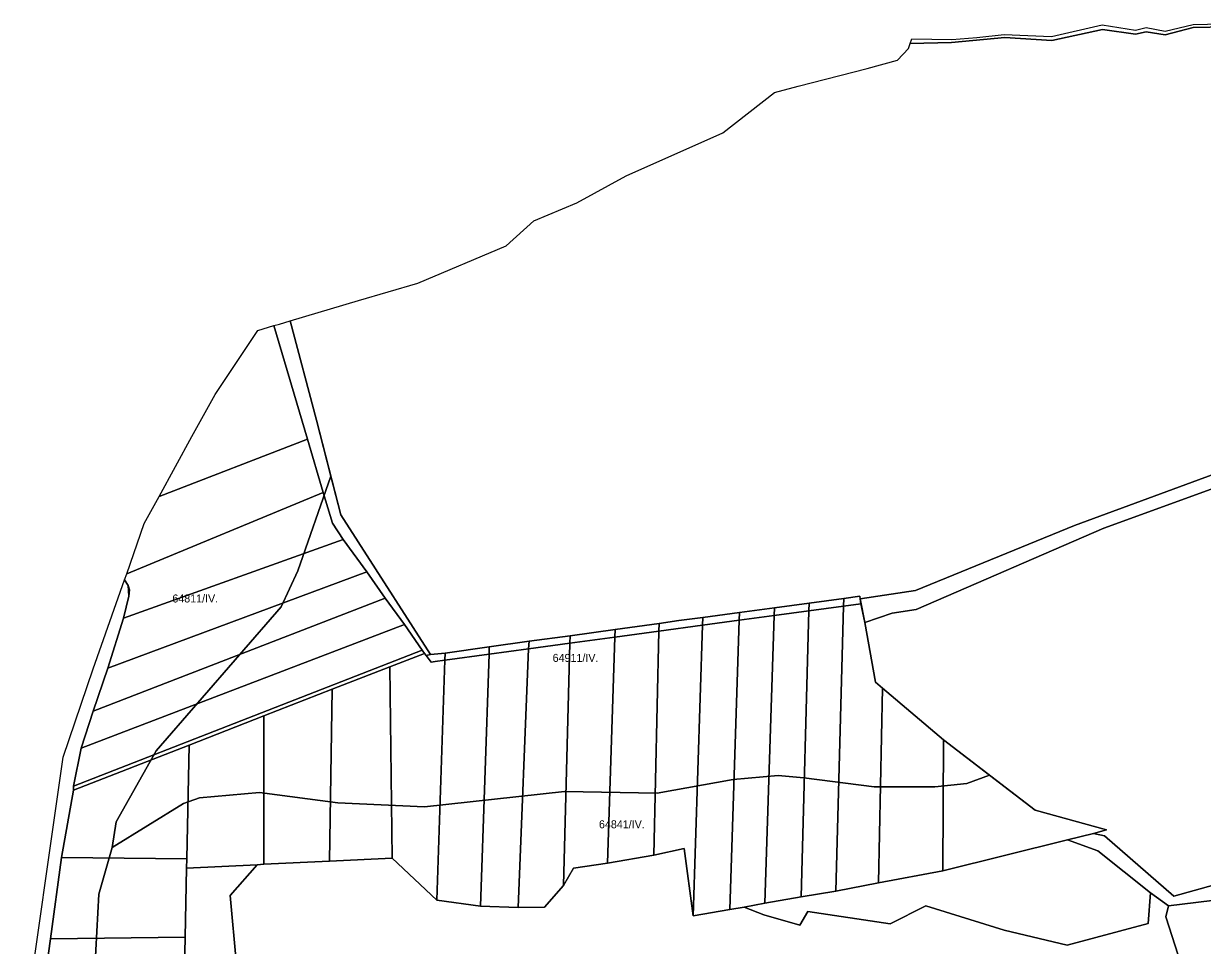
# Model space of a CAD drawing. Extents: x -521261 to -517465, y -1182764 to -1179456.
# Drawn here: x -521236 to -520500, y -1180889 to -1180313 of the extents above; entities that cross this region are included whole.
import ezdxf

# ---------------------------------------------------------------- set-up
doc = ezdxf.new("R2010")
doc.units = 0
for name, color, linetype in [('95560013', 7, 'Continuous'), ('95620013', 7, 'Continuous'), ('95630013', 7, 'Continuous'), ('95640013', 7, 'Continuous'), ('95660013', 7, 'Continuous')]:
    doc.layers.add(name, color=color, linetype=linetype)

msp = doc.modelspace()

# ---------------------------------------------------------------- linework, layer by layer
at = {"layer": '95560013'}
for points in [[(-521080, -1180501.82), (-521059.04, -1180572.8), (-521151.7, -1180608.67), (-521131.22, -1180571.13), (-521116.74, -1180544.81), (-521090.08, -1180504.84)], [(-521059.04, -1180572.8), (-521049.31, -1180606.17), (-521171.97, -1180656.94), (-521160.99, -1180625.55), (-521151.7, -1180608.67)], [(-521043.32, -1180625.33), (-521036.66, -1180635.53), (-521173.94, -1180684.6), (-521170.63, -1180670.86), (-521170.22, -1180666.94), (-521171, -1180664.15), (-521173.37, -1180660.62), (-521171.97, -1180656.94), (-521049.31, -1180606.17)], [(-521036.66, -1180635.53), (-521022.04, -1180655.73), (-521183.82, -1180715.79), (-521173.94, -1180684.6)], [(-521022.04, -1180655.73), (-521010.53, -1180672.06), (-521193.01, -1180742.64), (-521183.82, -1180715.79)], [(-521171, -1180664.15), (-521170.22, -1180666.94), (-521170.63, -1180670.86)], [(-521010.53, -1180672.06), (-520998.52, -1180688.54), (-521200.55, -1180765.87), (-521193.01, -1180742.64)], [(-520767.51, -1180682.98), (-520745.79, -1180680.06), (-520750.61, -1180858.87), (-520773.26, -1180862.77)], [(-520745.79, -1180680.06), (-520724.15, -1180677.17), (-520728.86, -1180855.3), (-520750.61, -1180858.87)], [(-520724.15, -1180677.17), (-520713.2, -1180675.69), (-520710.85, -1180687.4), (-520704.09, -1180724.52), (-520699.81, -1180728.35), (-520702.34, -1180849.97), (-520728.86, -1180855.3)], [(-520987.41, -1180704.59), (-521205.18, -1180789.6), (-521200.55, -1180765.87), (-520998.52, -1180688.54)], [(-520839.43, -1180692.75), (-520812.13, -1180689.06), (-520818.13, -1180870.65), (-520823.65, -1180828.61), (-520842.59, -1180832.65)], [(-520812.13, -1180689.06), (-520789.27, -1180685.97), (-520795.24, -1180866.73), (-520818.13, -1180870.65)], [(-520789.27, -1180685.97), (-520767.51, -1180682.98), (-520773.26, -1180862.77), (-520786.22, -1180865.2), (-520795.24, -1180866.73)], [(-520895.11, -1180700.28), (-520867, -1180696.48), (-520871.59, -1180837.65), (-520892.8, -1180840.93), (-520899.15, -1180851.67)], [(-520867, -1180696.48), (-520839.43, -1180692.75), (-520842.59, -1180832.65), (-520871.59, -1180837.65)], [(-520945.47, -1180707.08), (-520920.86, -1180703.75), (-520927.48, -1180865.42), (-520950.88, -1180864.7)], [(-520920.86, -1180703.75), (-520895.11, -1180700.28), (-520899.15, -1180851.67), (-520910.87, -1180865.15), (-520927.48, -1180865.42)], [(-520985.98, -1180706.63), (-521007.56, -1180714.96), (-521043.67, -1180729.02), (-521086.26, -1180745.67), (-521132.89, -1180763.92), (-521205.35, -1180792.14), (-521205.18, -1180789.6), (-520987.41, -1180704.59)], [(-520984.95, -1180708.02), (-520981.77, -1180712.2), (-520979.3, -1180711.65), (-520973.23, -1180710.84), (-520978.13, -1180860.76), (-521006.09, -1180834.57), (-521007.56, -1180714.96), (-520985.98, -1180706.63)], [(-520973.23, -1180710.84), (-520945.47, -1180707.08), (-520950.88, -1180864.7), (-520978.13, -1180860.76)], [(-521007.56, -1180714.96), (-521006.09, -1180834.57), (-521045.3, -1180836.39), (-521043.67, -1180729.02)], [(-521043.67, -1180729.02), (-521045.3, -1180836.39), (-521086.39, -1180838.41), (-521086.26, -1180745.67)], [(-520661.61, -1180760.58), (-520662.13, -1180842.53), (-520702.34, -1180849.97), (-520699.81, -1180728.35)], [(-521086.26, -1180745.67), (-521086.39, -1180838.41), (-521090.43, -1180838.7), (-521134.59, -1180840.77), (-521134.36, -1180835.02), (-521132.89, -1180763.92)], [(-520604.38, -1180804.7), (-520559.81, -1180816.94), (-520567.99, -1180819.26), (-520584.27, -1180823.22), (-520662.13, -1180842.53), (-520661.61, -1180760.58)], [(-521132.89, -1180763.92), (-521134.36, -1180835.02), (-521212.7, -1180834.19), (-521205.35, -1180792.14)], [(-521212.7, -1180834.19), (-521134.36, -1180835.02), (-521134.59, -1180840.77), (-521135.49, -1180884), (-521219.69, -1180885.08)], [(-521219.69, -1180885.08), (-521135.49, -1180884), (-521136.51, -1180932.9), (-521226.29, -1180932.9)]]:
    msp.add_lwpolyline(points, close=True, dxfattribs=at)
at = {"layer": '95620013'}
for points in [[(-520418.64, -1180567.25), (-520579.89, -1180626.79), (-520679.15, -1180667.26), (-520713.69, -1180672.62), (-520713.87, -1180670.87), (-520724.02, -1180672.26), (-520745.61, -1180675.16), (-520767.28, -1180678.06), (-520789.12, -1180681.02), (-520811.97, -1180684.15), (-520826.97, -1180686.18), (-520839.32, -1180687.91), (-520866.85, -1180691.76), (-520894.99, -1180695.67), (-520920.54, -1180699.08), (-520945.52, -1180702.45), (-520972.99, -1180706.39), (-520982.12, -1180707.29), (-521027.44, -1180636.91), (-521038.23, -1180619.96), (-521053.35, -1180560.82), (-521069.84, -1180498.79), (-521027.14, -1180486), (-520990.12, -1180475.22), (-520934.86, -1180451.88), (-520917.68, -1180436.32), (-520890.7, -1180425.05), (-520859.95, -1180408.13), (-520799.56, -1180381.23), (-520767.33, -1180356.04), (-520752.44, -1180352.25), (-520709.38, -1180341.01), (-520690.43, -1180335.96), (-520683.47, -1180328.57), (-520682.5, -1180325.44), (-520656.71, -1180324.81), (-520623.24, -1180321.76), (-520593.96, -1180323.61), (-520562.36, -1180316.64), (-520541.7, -1180319.56), (-520535.11, -1180318.28), (-520523.12, -1180320.04), (-520505.71, -1180315.43), (-520463.59, -1180314.64)], [(-520437.72, -1180836.09), (-520517.73, -1180858.28), (-520561.06, -1180820.59), (-520567.99, -1180819.26), (-520559.81, -1180816.94), (-520604.38, -1180804.7), (-520661.61, -1180760.58), (-520699.81, -1180728.35), (-520704.09, -1180724.52), (-520710.85, -1180687.4), (-520693.72, -1180681.5), (-520678.77, -1180679.14), (-520561.44, -1180628.41), (-520418.21, -1180576.2)], [(-521103.44, -1180901.21), (-521107.32, -1180858.01), (-521090.43, -1180838.7), (-521086.39, -1180838.41), (-521045.3, -1180836.39), (-521006.09, -1180834.57), (-520978.13, -1180860.76), (-520950.88, -1180864.7), (-520927.48, -1180865.42), (-520910.87, -1180865.15), (-520899.15, -1180851.67), (-520892.8, -1180840.93), (-520871.59, -1180837.65), (-520842.59, -1180832.65), (-520823.65, -1180828.61), (-520818.13, -1180870.65), (-520795.24, -1180866.73), (-520786.22, -1180865.2), (-520774, -1180870.09), (-520751.46, -1180876.46), (-520746.46, -1180867.85), (-520695.02, -1180875.69), (-520672.62, -1180864.44), (-520623.79, -1180879.69), (-520584.43, -1180888.95), (-520533.79, -1180875.34), (-520532.28, -1180856.24), (-520521.14, -1180864.38), (-520522.73, -1180871.37), (-520514.96, -1180895.18)]]:
    msp.add_lwpolyline(points, dxfattribs=at)
for points in [[(-520584.27, -1180823.22), (-520565.24, -1180830.11), (-520532.28, -1180856.24), (-520533.79, -1180875.34), (-520584.43, -1180888.95), (-520623.79, -1180879.69), (-520672.62, -1180864.44), (-520695.02, -1180875.69), (-520746.46, -1180867.85), (-520751.46, -1180876.46), (-520774, -1180870.09), (-520786.22, -1180865.2), (-520773.26, -1180862.77), (-520750.61, -1180858.87), (-520728.86, -1180855.3), (-520702.34, -1180849.97), (-520662.13, -1180842.53)], [(-521134.59, -1180840.77), (-521090.43, -1180838.7), (-521107.32, -1180858.01), (-521103.44, -1180901.21), (-521041.31, -1180920.9), (-521041.32, -1180957.03), (-521041.57, -1181004.34), (-521124.61, -1180969.86), (-521161.12, -1181167.95), (-521159.23, -1181119.6), (-521158.27, -1181073.9), (-521149.47, -1181024.96), (-521139.18, -1180978.59), (-521137.03, -1180959.08), (-521136.51, -1180932.9), (-521135.49, -1180884)], [(-520447.63, -1180855.08), (-520441.44, -1180872.23), (-520413.63, -1180886.67), (-520437.74, -1180886.84), (-520450.85, -1180888.84), (-520466.27, -1180947.66), (-520479.73, -1180952.5), (-520490.67, -1180954.03), (-520505.09, -1180945.85), (-520508.85, -1180907.38), (-520510.51, -1180896.3), (-520514.96, -1180895.18), (-520522.73, -1180871.37), (-520521.14, -1180864.38), (-520485.24, -1180860)]]:
    msp.add_lwpolyline(points, close=True, dxfattribs=at)
at = {"layer": '95630013'}
msp.add_lwpolyline([(-520463.59, -1180314.64), (-520505.71, -1180315.43), (-520523.12, -1180320.04), (-520535.11, -1180318.28), (-520541.7, -1180319.56), (-520562.36, -1180316.64), (-520593.96, -1180323.61), (-520623.24, -1180321.76), (-520656.71, -1180324.81), (-520682.5, -1180325.44), (-520681.46, -1180322.66), (-520656.46, -1180322.89), (-520640.91, -1180321.65), (-520623.67, -1180319.82), (-520594.16, -1180321.19), (-520562.44, -1180313.88), (-520541.65, -1180317.16), (-520534.97, -1180315.56), (-520523.11, -1180317.8), (-520505.74, -1180313.71), (-520478.98, -1180313.03)], dxfattribs=at)
at = {"layer": '95640013'}
for points in [[(-521069.84, -1180498.79), (-521053.35, -1180560.82), (-521038.23, -1180619.96), (-521027.44, -1180636.91), (-520982.12, -1180707.29), (-520984.95, -1180708.02), (-520985.98, -1180706.63), (-520987.41, -1180704.59), (-520998.52, -1180688.54), (-521010.53, -1180672.06), (-521022.04, -1180655.73), (-521036.66, -1180635.53), (-521043.32, -1180625.33), (-521049.31, -1180606.17), (-521059.04, -1180572.8), (-521080, -1180501.82), (-521076.54, -1180500.79)], [(-520724.02, -1180672.26), (-520724.15, -1180677.17), (-520745.79, -1180680.06), (-520745.61, -1180675.16)], [(-520713.87, -1180670.87), (-520713.69, -1180672.62), (-520713.2, -1180675.69), (-520724.15, -1180677.17), (-520724.02, -1180672.26)], [(-520789.12, -1180681.02), (-520789.27, -1180685.97), (-520812.13, -1180689.06), (-520811.97, -1180684.15)], [(-520767.28, -1180678.06), (-520767.51, -1180682.98), (-520789.27, -1180685.97), (-520789.12, -1180681.02)], [(-520745.61, -1180675.16), (-520745.79, -1180680.06), (-520767.51, -1180682.98), (-520767.28, -1180678.06)], [(-520839.32, -1180687.91), (-520839.43, -1180692.75), (-520867, -1180696.48), (-520866.85, -1180691.76)], [(-520826.97, -1180686.18), (-520811.97, -1180684.15), (-520812.13, -1180689.06), (-520839.43, -1180692.75), (-520839.32, -1180687.91)], [(-520894.99, -1180695.67), (-520895.11, -1180700.28), (-520920.86, -1180703.75), (-520920.54, -1180699.08)], [(-520866.85, -1180691.76), (-520867, -1180696.48), (-520895.11, -1180700.28), (-520894.99, -1180695.67)], [(-520945.52, -1180702.45), (-520945.47, -1180707.08), (-520973.23, -1180710.84), (-520972.99, -1180706.39)], [(-520920.54, -1180699.08), (-520920.86, -1180703.75), (-520945.47, -1180707.08), (-520945.52, -1180702.45)], [(-520982.12, -1180707.29), (-520972.99, -1180706.39), (-520973.23, -1180710.84), (-520979.3, -1180711.65), (-520981.77, -1180712.2), (-520984.95, -1180708.02)], [(-520080.76, -1180777.95), (-520075.86, -1180795.03), (-520153.4, -1180806.35), (-520296.21, -1180829.93), (-520440.58, -1180853.57), (-520447.63, -1180855.08), (-520485.24, -1180860), (-520521.14, -1180864.38), (-520532.28, -1180856.24), (-520565.24, -1180830.11), (-520584.27, -1180823.22), (-520567.99, -1180819.26), (-520561.06, -1180820.59), (-520517.73, -1180858.28), (-520437.72, -1180836.09), (-520260.96, -1180807.27)]]:
    msp.add_lwpolyline(points, close=True, dxfattribs=at)
for points in [[(-520418.21, -1180576.2), (-520561.44, -1180628.41), (-520678.77, -1180679.14), (-520693.72, -1180681.5), (-520710.85, -1180687.4), (-520713.2, -1180675.69), (-520713.69, -1180672.62), (-520679.15, -1180667.26), (-520579.89, -1180626.79), (-520418.64, -1180567.25)], [(-521236.44, -1180945.21), (-521211.68, -1180771.41), (-521193.04, -1180716.3), (-521173.37, -1180660.62), (-521171, -1180664.15), (-521170.63, -1180670.86), (-521173.94, -1180684.6), (-521183.82, -1180715.79), (-521193.01, -1180742.64), (-521200.55, -1180765.87), (-521205.18, -1180789.6), (-521205.35, -1180792.14), (-521212.7, -1180834.19), (-521219.69, -1180885.08), (-521226.29, -1180932.9)]]:
    msp.add_lwpolyline(points, dxfattribs=at)
at = {"layer": '95660013'}
for points in [[(-521136.51, -1180932.9), (-521135.49, -1180884), (-521134.59, -1180840.77), (-521090.43, -1180838.7), (-521086.39, -1180838.41), (-521045.3, -1180836.39), (-521006.09, -1180834.57), (-520978.13, -1180860.76), (-520950.88, -1180864.7), (-520927.48, -1180865.42), (-520910.87, -1180865.15), (-520899.15, -1180851.67), (-520892.8, -1180840.93), (-520871.59, -1180837.65), (-520842.59, -1180832.65), (-520823.65, -1180828.61), (-520818.13, -1180870.65), (-520795.24, -1180866.73), (-520786.22, -1180865.2), (-520773.26, -1180862.77), (-520750.61, -1180858.87), (-520728.86, -1180855.3), (-520702.34, -1180849.97), (-520662.13, -1180842.53), (-520584.27, -1180823.22), (-520567.99, -1180819.26), (-520559.81, -1180816.94), (-520604.38, -1180804.7), (-520632.9, -1180782.71), (-520661.61, -1180760.58), (-520699.81, -1180728.35), (-520704.09, -1180724.52), (-520710.85, -1180687.4), (-520713.69, -1180672.62), (-520713.87, -1180670.87), (-520724.02, -1180672.26), (-520745.61, -1180675.16), (-520767.28, -1180678.06), (-520789.12, -1180681.02), (-520811.97, -1180684.15), (-520826.97, -1180686.18), (-520839.32, -1180687.91), (-520866.85, -1180691.76), (-520894.99, -1180695.67), (-520920.54, -1180699.08), (-520945.52, -1180702.45), (-520972.99, -1180706.39), (-520982.12, -1180707.29), (-521027.44, -1180636.91), (-521038.23, -1180619.96), (-521044.38, -1180595.9), (-521053.35, -1180560.82), (-521069.84, -1180498.79), (-521027.14, -1180486), (-520990.12, -1180475.22), (-520934.86, -1180451.88), (-520917.68, -1180436.32), (-520890.7, -1180425.05), (-520859.95, -1180408.13), (-520799.56, -1180381.23), (-520767.33, -1180356.04), (-520752.44, -1180352.25), (-520709.38, -1180341.01), (-520690.43, -1180335.96), (-520683.47, -1180328.57), (-520682.5, -1180325.44), (-520681.46, -1180322.66), (-520656.46, -1180322.89), (-520640.91, -1180321.65), (-520623.67, -1180319.82), (-520594.16, -1180321.19), (-520562.44, -1180313.88), (-520541.65, -1180317.16), (-520534.97, -1180315.56), (-520523.11, -1180317.8), (-520505.74, -1180313.71), (-520478.98, -1180313.03)], [(-521236.44, -1180945.21), (-521211.68, -1180771.41), (-521193.04, -1180716.3), (-521173.37, -1180660.62), (-521171.97, -1180656.94), (-521160.99, -1180625.55), (-521151.7, -1180608.67), (-521131.22, -1180571.13), (-521120.83, -1180552.25), (-521116.74, -1180544.81), (-521090.08, -1180504.84), (-521080, -1180501.82), (-521076.54, -1180500.79), (-521069.84, -1180498.79), (-521053.35, -1180560.82), (-521044.38, -1180595.9), (-521065, -1180655), (-521075.5, -1180677.5), (-521153.5, -1180767.5), (-521178.5, -1180812), (-521181, -1180828), (-521189.5, -1180857), (-521192.5, -1180915.5)], [(-521192.5, -1180915.5), (-521189.5, -1180857), (-521181, -1180828), (-521136.5, -1180800.5), (-521126.5, -1180797), (-521089, -1180793.5), (-521040, -1180800), (-520986, -1180802.5), (-520898.5, -1180793), (-520840.5, -1180794), (-520793, -1180785.5), (-520765, -1180783), (-520749, -1180784.5), (-520705, -1180790), (-520667, -1180790), (-520647, -1180788), (-520632.9, -1180782.71), (-520604.38, -1180804.7), (-520559.81, -1180816.94), (-520567.99, -1180819.26), (-520584.27, -1180823.22), (-520662.13, -1180842.53), (-520702.34, -1180849.97), (-520728.86, -1180855.3), (-520750.61, -1180858.87), (-520773.26, -1180862.77), (-520786.22, -1180865.2), (-520795.24, -1180866.73), (-520818.13, -1180870.65), (-520823.65, -1180828.61), (-520842.59, -1180832.65), (-520871.59, -1180837.65), (-520892.8, -1180840.93), (-520899.15, -1180851.67), (-520910.87, -1180865.15), (-520927.48, -1180865.42), (-520950.88, -1180864.7), (-520978.13, -1180860.76), (-521006.09, -1180834.57), (-521045.3, -1180836.39), (-521086.39, -1180838.41), (-521090.43, -1180838.7), (-521134.59, -1180840.77), (-521135.49, -1180884), (-521136.51, -1180932.9)]]:
    msp.add_lwpolyline(points, dxfattribs=at)
msp.add_lwpolyline([(-521065, -1180655), (-521044.38, -1180595.9), (-521038.23, -1180619.96), (-521027.44, -1180636.91), (-520982.12, -1180707.29), (-520972.99, -1180706.39), (-520945.52, -1180702.45), (-520920.54, -1180699.08), (-520894.99, -1180695.67), (-520866.85, -1180691.76), (-520839.32, -1180687.91), (-520826.97, -1180686.18), (-520811.97, -1180684.15), (-520789.12, -1180681.02), (-520767.28, -1180678.06), (-520745.61, -1180675.16), (-520724.02, -1180672.26), (-520713.87, -1180670.87), (-520713.69, -1180672.62), (-520710.85, -1180687.4), (-520704.09, -1180724.52), (-520699.81, -1180728.35), (-520661.61, -1180760.58), (-520632.9, -1180782.71), (-520647, -1180788), (-520667, -1180790), (-520705, -1180790), (-520749, -1180784.5), (-520765, -1180783), (-520793, -1180785.5), (-520840.5, -1180794), (-520898.5, -1180793), (-520986, -1180802.5), (-521040, -1180800), (-521089, -1180793.5), (-521126.5, -1180797), (-521136.5, -1180800.5), (-521181, -1180828), (-521178.5, -1180812), (-521153.5, -1180767.5), (-521075.5, -1180677.5)], close=True, dxfattribs=at)

# ---------------------------------------------------------------- texts
for s, rotation, p in [('64811/IV.', 360, (-521143.5, -1180674.81)), ('64911/IV.', 0, (-520905.87, -1180711.95)), ('64841/IV.', 0, (-520876.91, -1180815.92))]:
    msp.add_text(s, height=5, rotation=rotation, dxfattribs=at).set_placement(p)

doc.saveas('drawing.dxf')
